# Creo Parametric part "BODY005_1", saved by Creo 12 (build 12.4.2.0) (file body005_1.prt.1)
Units: Custom; MM, KILOGRAM, SECS

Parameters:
  PTC_WM_ITERATION = "0"
  PTC_WM_VERSION = "-.0"
  PTC_WM_LIFECYCLE_STATE = "In Work"
  PTC_WM_LIFECYCLE = "MO_CADDocument"
  PTC_WM_CREATED_BY = "Maximilian Roepper (Z0017RMS: MO)"
  PTC_WM_CREATED_ON = "18-Sep-26 11:36:42 AM"
  PTC_WM_MODIFIED_BY = "Maximilian Roepper (Z0017RMS: MO)"
  PTC_WM_MODIFIED_ON = "18-Sep-26 11:36:46 AM"
  PDMLINKNUMBER = "PDM000071455336"
  PTC_WM_NAME = "body005_1.prt"
  PTC_WM_NUMBER = "PDM000071455336"

Other parameters: WEIGHT, WEIGHT_FACTOR, WEIGHT_ADD, _MASS_TEMP, _DIFF_TEMP, MC_ERRORS, SUPPLIER

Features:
  1. coordinate system
  2. datum plane "PRT_YZ"
  3. datum plane "PRT_XY"
  4. datum plane "PRT_XZ"
  5. coordinate system
  6. datum axis
  7. datum axis
  8. datum axis
  9. coordinate system
  10. imported feature

Other named items: PRT, SIEMENS_MO, DRW_VIEW_ORG, PRT_X, PRT_Y, PRT_Z, CS0, ROUGH_GROB

Layers: 00_STD_CSYS-KSYS, 01_STD_PLANES-EBENEN, 02_STD_AXES-ACHSEN, 03_STD_CSYS-KSYS, 24_IMPORT_FEAT-IMPORT_KE

Surfaces: 6 plane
